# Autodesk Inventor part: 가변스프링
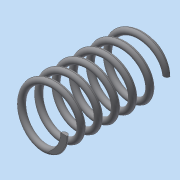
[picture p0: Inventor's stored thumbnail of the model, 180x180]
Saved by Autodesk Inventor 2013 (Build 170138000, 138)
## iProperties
Created: 2018-07
Part Number: 가변스프링
Material: 일반
Document SubType Name: Modeling
Designer: dgall
Density: 1 g/cm^3
Author: dgall
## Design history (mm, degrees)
sketch "스케치1"
  geometry: L1 (0, 0)-(0, 32.5); L2 (0, 0)-(8, 0); L3 (0, 32.5)-(8, 32.5); C1 r 1 at (8, 0)
  constraints: 6 end point, 2 parallel, 1 centre point, 1 coincident, 1 perpendicular, 1 vertical
  dimensions: "d0" = 32.5 distance of L1.start L1.end (derived); "d1" = 16 diameter of L2.end L1; "d2" = 2 diameter of C1
feature "코일1" pitch "d3" = 10; turns "d5" = 6; dims "d4" = 32.5 (= d0), "d6" = 0, angle "d7" = 90 deg, angle "d8" = 90 deg, "d9" = 0, "d10" = 0
feature "분할1"
node "작업 평면1"
feature "분할2"
node "솔리드1"
